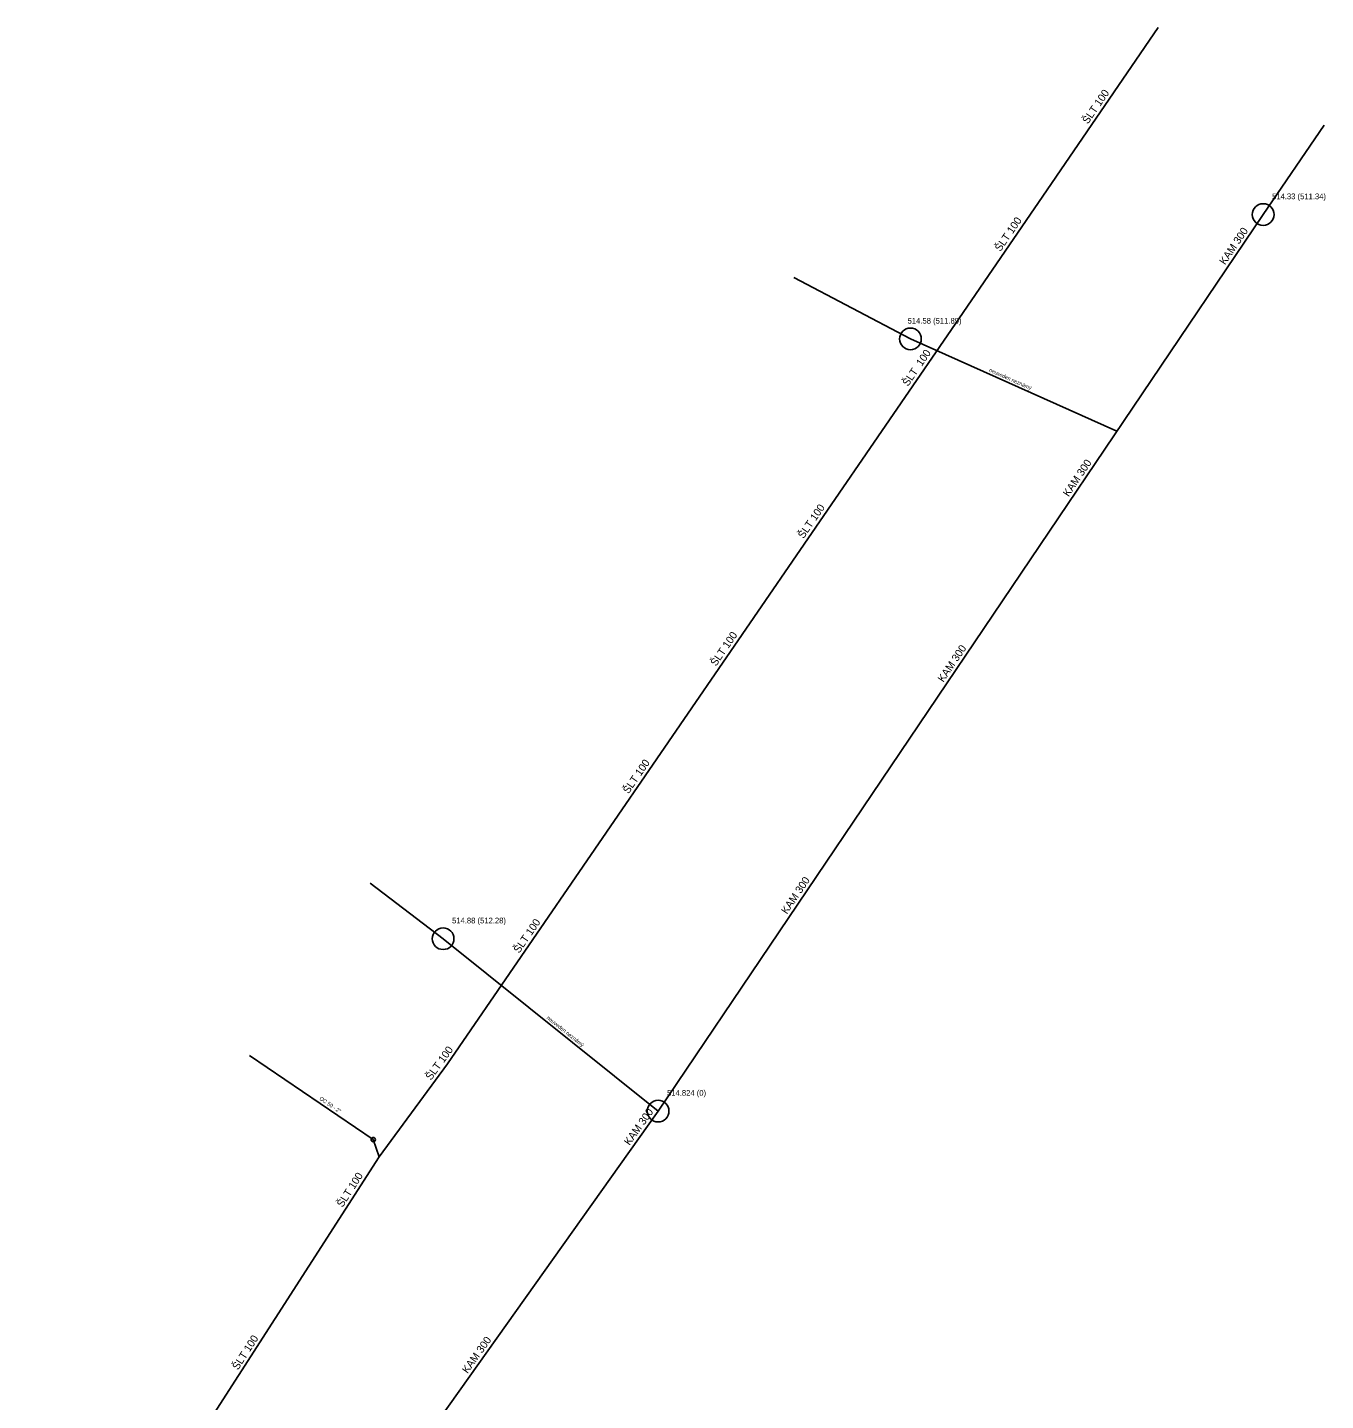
# Model space of a CAD drawing. Extents: x -668995 to -668929, y -1128059 to -1127935.
# Drawn here: x -668958.42 to -668928.51, y -1127966.43 to -1127934.77 of the extents above; entities that cross this region are included whole.
import ezdxf

# ---------------------------------------------------------------- set-up
doc = ezdxf.new("R2010")
doc.units = 0
for name, color, linetype in [('Implicitní', 7, 'Continuous'), ('JEDN_D', 7, 'Continuous'), ('JEDN_O', 7, 'Continuous'), ('k_sachta_clip_Layer', 7, 'Continuous'), ('k_sachta_clip_LayerAnotace', 7, 'Continuous'), ('k_sachta_o', 7, 'Continuous'), ('kanal_clip_LayerAnotace', 7, 'Continuous'), ('soupe_o', 7, 'Continuous'), ('VOD_D', 7, 'Continuous'), ('VOD_O', 7, 'Continuous'), ('vodovod_clip_LayerAnotace', 7, 'Continuous')]:
    doc.layers.add(name, color=color, linetype=linetype)

msp = doc.modelspace()

# ---------------------------------------------------------------- linework, layer by layer
at = {"layer": 'JEDN_D'}
for p, q in [((-668929.945, -1127939.08), (-668928.542, -1127937.018)), ((-668943.89, -1127959.755), (-668929.945, -1127939.08)), ((-668956.53, -1127977.56), (-668943.89, -1127959.755))]:
    msp.add_line(p, q, dxfattribs=at)
at = {"layer": 'JEDN_O'}
for points in [[(-668933.315, -1127944.076), (-668938.074, -1127941.949), (-668940.76, -1127940.53)], [(-668943.89, -1127959.755), (-668948.845, -1127955.78), (-668950.525, -1127954.498)]]:
    msp.add_lwpolyline(points, dxfattribs=at)
at = {"layer": 'k_sachta_clip_Layer'}
for p, q in [((-668929.945, -1127939.08), (-668929.945, -1127939.08)), ((-668938.074, -1127941.949), (-668938.074, -1127941.949)), ((-668948.845, -1127955.78), (-668948.845, -1127955.78)), ((-668943.89, -1127959.755), (-668943.89, -1127959.755))]:
    msp.add_line(p, q, dxfattribs=at)
at = {"layer": 'k_sachta_o'}
for centre in [(-668929.945, -1127939.08), (-668938.074, -1127941.949), (-668948.845, -1127955.78), (-668943.89, -1127959.755)]:
    msp.add_circle(centre, 0.25, dxfattribs=at)
at = {"layer": 'soupe_o'}
msp.add_circle((-668950.454, -1127960.413), 0.05, dxfattribs=at)
at = {"layer": 'VOD_D'}
msp.add_lwpolyline([(-668950.322, -1127960.812), (-668948.744, -1127958.662), (-668936.858, -1127941.336), (-668935.021, -1127938.658), (-668932.363, -1127934.766)], dxfattribs=at)
at = {"layer": 'VOD_O'}
for points in [[(-668950.322, -1127960.812), (-668950.454, -1127960.413), (-668953.304, -1127958.474)], [(-668958.425, -1127973.525), (-668957.578, -1127972.102), (-668950.322, -1127960.812)]]:
    msp.add_lwpolyline(points, dxfattribs=at)

# ---------------------------------------------------------------- texts
at = {"layer": 'Implicitní'}
msp.add_text('ŠLT  100', height=0.1755, rotation=55.5689, dxfattribs=at).set_placement((-668938.131, -1127943.055))
at = {"layer": 'k_sachta_clip_LayerAnotace'}
for s, p in [('514.33 (511.34)', (-668929.74, -1127938.727)), ('514.58 (511.89)', (-668938.14, -1127941.596)), ('514.88 (512.28)', (-668948.64, -1127955.427)), ('514.824 (0)', (-668943.685, -1127959.402))]:
    msp.add_text(s, height=0.13163, dxfattribs=at).set_placement(p)
at = {"layer": 'kanal_clip_LayerAnotace'}
for s, height, rotation, p in [('KAM 300', 0.1755, 56.0009, (-668930.822, -1127940.254)), ('neuveden neznámý', 0.08776, 335.9182, (-668936.271, -1127942.697)), ('KAM 300', 0.1755, 56.0007, (-668934.429, -1127945.602)), ('KAM 300', 0.1755, 56.0011, (-668937.315, -1127949.88)), ('KAM 300', 0.1755, 56.0004, (-668940.922, -1127955.228)), ('neuveden neznámý', 0.08776, 321.2628, (-668946.466, -1127957.62)), ('KAM 300', 0.1755, 54.6287, (-668944.548, -1127960.56)), ('KAM 300', 0.1755, 54.6292, (-668948.282, -1127965.82))]:
    msp.add_text(s, height=height, rotation=rotation, dxfattribs=at).set_placement(p)
at = {"layer": 'vodovod_clip_LayerAnotace'}
for s, height, rotation, p in [('ŠLT 100', 0.1755, 55.569, (-668933.984, -1127937.005)), ('ŠLT 100', 0.1755, 55.569, (-668936.001, -1127939.947)), ('ŠLT 100', 0.1755, 55.569, (-668940.539, -1127946.567)), ('ŠLT 100', 0.1755, 55.569, (-668942.555, -1127949.509)), ('ŠLT 100', 0.1755, 55.5697, (-668944.572, -1127952.452)), ('ŠLT 100', 0.1755, 55.569, (-668947.093, -1127956.129)), ('ŠLT 100', 0.1755, 53.9655, (-668949.125, -1127959.058)), ('OC 50 - 2"', 0.0878, 325.7781, (-668951.707, -1127959.486)), ('ŠLT 100', 0.1755, 57.2707, (-668951.163, -1127961.989)), ('ŠLT 100', 0.1755, 57.2707, (-668953.573, -1127965.74))]:
    msp.add_text(s, height=height, rotation=rotation, dxfattribs=at).set_placement(p)

doc.saveas('drawing.dxf')
